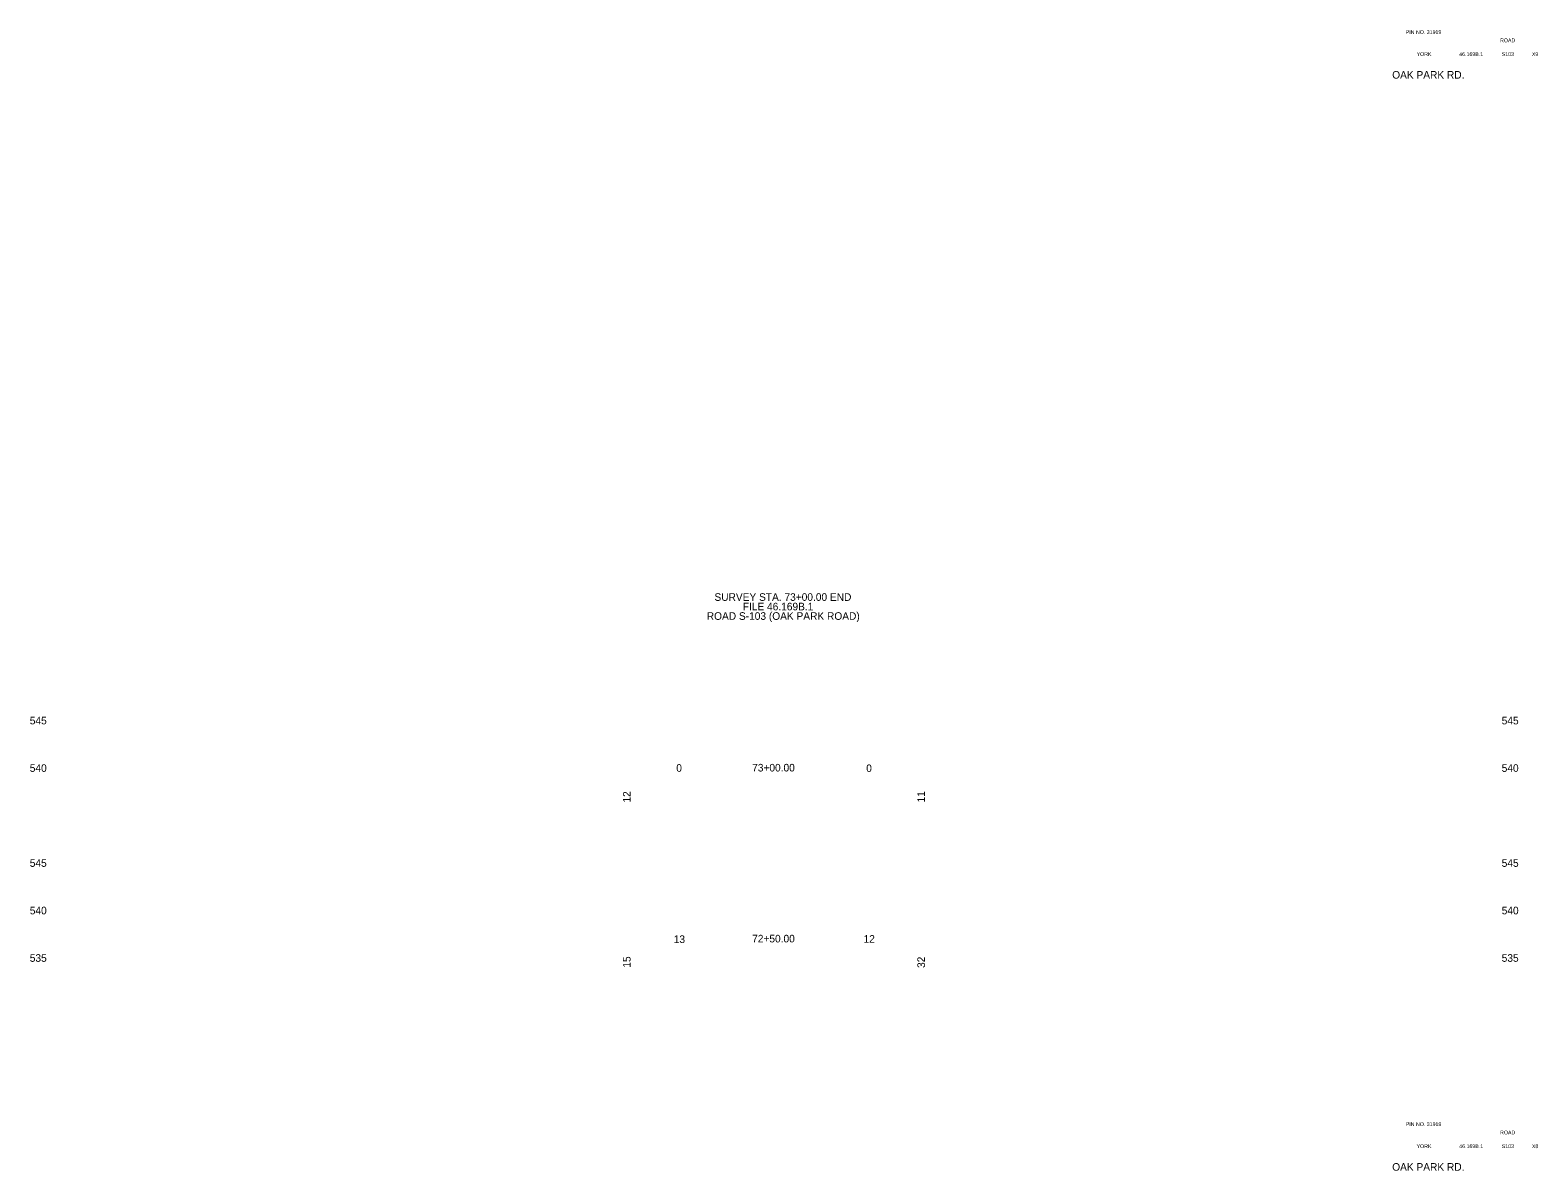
# Model space of a CAD drawing. Extents: x 1002 to 1160, y 1001 to 2023.
# Drawn here: x 1001.7 to 1160.4, y 1903.1 to 2023.2 of the extents above; entities that cross this region are included whole.
import ezdxf

# ---------------------------------------------------------------- set-up
doc = ezdxf.new("R2010")
doc.units = 0
for name, color, linetype in [('Level 20', 7, 'Continuous'), ('Level 21', 7, 'Continuous'), ('Level 22', 7, 'Continuous'), ('Level 23', 7, 'Continuous'), ('Level 25', 7, 'Continuous'), ('Level 41', 7, 'Continuous'), ('Level 56', 7, 'Continuous')]:
    doc.layers.add(name, color=color, linetype=linetype)

msp = doc.modelspace()

# ---------------------------------------------------------------- texts
at = {"layer": 'Level 20'}
for s, p in [('0', (1069.71, 1945.11)), ('13', (1069.44, 1927.08))]:
    msp.add_text(s, height=0.8, dxfattribs=at).set_placement(p)
at = {"layer": 'Level 21'}
for s, p in [('12', (1064.9, 1941.87)), ('15', (1064.9, 1924.48))]:
    msp.add_text(s, height=0.8, rotation=90, dxfattribs=at).set_placement(p)
at = {"layer": 'Level 22'}
for s, p in [('0', (1089.71, 1945.08)), ('12', (1089.43, 1927.11))]:
    msp.add_text(s, height=0.8, dxfattribs=at).set_placement(p)
at = {"layer": 'Level 23'}
for s, p in [('11', (1095.9, 1941.88)), ('32', (1095.9, 1924.45))]:
    msp.add_text(s, height=0.8, rotation=90, dxfattribs=at).set_placement(p)
at = {"layer": 'Level 25'}
for s, p in [('73+00.00', (1077.7, 1945.14)), ('72+50.00', (1077.7, 1927.14))]:
    msp.add_text(s, height=0.8, dxfattribs=at).set_placement(p)
at = {"layer": 'Level 41'}
for s, height, p in [('PIN NO. 31919', 0.4, (1146.53, 2022.8)), ('ROAD', 0.4, (1156.46, 2021.93)), ('YORK', 0.4, (1147.67, 2020.48)), ('46.169B.1', 0.4, (1152.16, 2020.48)), ('S103', 0.4, (1156.63, 2020.48)), ('X9', 0.4, (1159.81, 2020.48)), ('OAK PARK RD.', 0.8, (1145.1, 2018.1)), ('SURVEY STA. 73+00.00 END', 0.8, (1073.73, 1963.11)), ('FILE 46.169B.1', 0.8, (1076.71, 1962.11)), ('ROAD S-103 (OAK PARK ROAD)', 0.8, (1072.92, 1961.11)), ('PIN NO. 31919', 0.4, (1146.53, 1907.8)), ('ROAD', 0.4, (1156.46, 1906.93)), ('YORK', 0.4, (1147.67, 1905.48)), ('46.169B.1', 0.4, (1152.16, 1905.48)), ('S103', 0.4, (1156.63, 1905.48)), ('X8', 0.4, (1159.81, 1905.48)), ('OAK PARK RD.', 0.8, (1145.1, 1903.1))]:
    msp.add_text(s, height=height, dxfattribs=at).set_placement(p)
at = {"layer": 'Level 56'}
for s, p in [('545', (1001.63, 1950.1)), ('545', (1156.63, 1950.1)), ('540', (1001.63, 1945.1)), ('540', (1156.63, 1945.1)), ('545', (1001.63, 1935.1)), ('545', (1156.63, 1935.1)), ('540', (1001.63, 1930.1)), ('540', (1156.63, 1930.1)), ('535', (1001.63, 1925.1)), ('535', (1156.63, 1925.1))]:
    msp.add_text(s, height=0.8, dxfattribs=at).set_placement(p)

doc.saveas('drawing.dxf')
